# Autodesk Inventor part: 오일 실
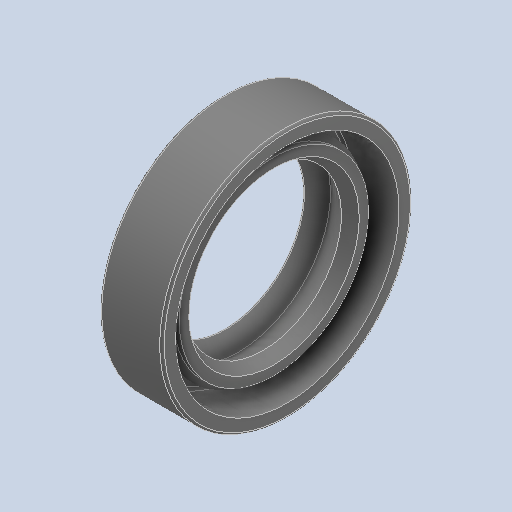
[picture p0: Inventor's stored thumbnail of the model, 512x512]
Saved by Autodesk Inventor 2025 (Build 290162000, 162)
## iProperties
Created: 2025-08
Part Number: 오일 실
Material: 고무
Description: 오일-실
Document SubType Name: Modeling
Designer: infra02
Density: 0.93 g/cm^3
Appearance: 기본값
Author: jhkim
Sending System: Autodesk Inventor 2026
Preprocessor: ST-DEVELOPER v20.1
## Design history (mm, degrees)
feature "Solid1"
node "솔리드1"
